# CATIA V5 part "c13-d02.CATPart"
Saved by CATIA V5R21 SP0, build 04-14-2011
Part number: Part1
Bounding box of the stored display mesh (mm): x -33 to 33, y -200.819 to 48, z -35 to 35
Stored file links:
  D:\CATIA V5R21 E-RESOURCES\CATIA-V5R21\catia-v5r21-prt\c13-catia-v5r20-prt\c13-catia-v5r20-figr-13-12 & 13\cat_v5r21_c13-d02.CATPart
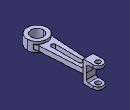
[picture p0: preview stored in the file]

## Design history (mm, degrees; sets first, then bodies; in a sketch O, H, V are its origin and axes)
Body1 (main body)
  Sketch1 on yz-plane, origin (0, 0, 0), H (0, 1, 0), V (0, 0, 1)
    line L1 (0, 0) -> (0, -35)
    point P1 (0, -35)
    line L2 (0, -35) -> (48, -35)
    point P2 (48, -35)
    line L3 (48, -35) -> (48, -25)
    point P3 (48, -25)
    line L4 (48, -25) -> (10, -25)
    point P4 (10, -25)
    line L5 (10, -25) -> (10, 0)
    point P5 (10, 0)
    point P6 (0, 0)
    point P7 (0, 0)
    point P8 (0, 35)
    point P9 (48, 35)
    point P10 (48, 25)
    point P11 (10, 25)
    point P12 (10, 0)
    point P13 (0, 0)
    line L6 (0, 0) -> (0, 35)
    line L7 (0, 35) -> (48, 35)
    line L8 (48, 35) -> (48, 25)
    line L9 (48, 25) -> (10, 25)
    line L10 (10, 25) -> (10, 0)
    length L8 = 10
    distance P3 L9 = 50
    length L2 = 48
    distance L10 L6 = 10
    vertical: L1 V, L3 V, L5 V
    horizontal: L2 H, L4 H
    symmetry: O P7 H, P1 P8 H, P2 P9 H, P3 P10 H, P4 P11 H, P5 P12 H, P6 P13 H, L1 L6 H, L2 L7 H, L3 L8 H, L4 L9 H, L5 L10 H
    coincidence: P13 P7, P12 P5, P6 P7
  Pad1: profile Sketch1, direction (1, 0, 0), length 16, mirrored extent
  Sketch2 on xy-plane, origin (0, 0, 0), H (1, 0, 0), V (0, 1, 0)
    circle A1 centre (0, -168) radius 33
    point P1 (0, -168)
    circle A2 centre (0, -168) radius 20
    distance P1 H = 168
    radius A1 = 33
    radius A2 = 20
    coincidence: P1 V
  Pad2: profile Sketch2, direction (0, 0, 1), length 16, mirrored extent
  Sketch3 on xy-plane, origin (0, 0, 0), H (1, 0, 0), V (0, 1, 0)
    line L1 (-16, 0) -> (-25, -146.4593)
    point P1 (-16, 0)
    point P2 (-25, -146.4593)
    line L2 (16, 0) -> (25, -146.4593)
    point P3 (16, 0)
    point P4 (25, -146.4593)
    reference projected line E1 (16, 48) -> (16, 0) from edge [face of Pad1 | face of Pad1]
    reference projected line E2 (-16, 48) -> (-16, 0) from edge [face of Pad1 | face of Pad1]
    projected circle E3 centre (0, -168) radius 33 from edge [face of Pad2 | face of Pad2]
    projected arc E4 centre (0, -168) radius 33 from (25, -146.4593) to (-25, -146.4593) ccw from edge [face of Pad2 | face of Pad2]
    line L3 (-16, 0) -> (16, 0)
    distance P4 P2 H = 50
    coincidence: P1 H, P3 H, P3 E1, P1 E2, P2 E3, P4 E3
    symmetry: P4 P2 V
    horizontal: L3 H
  Pad3: profile Sketch3, direction (0, 0, 1), length 8, mirrored extent
  Fillet1: radius 6, on edge [face of Pad1 | face of Pad3]; edge [face of Pad3 | face of Pad1]; edge [face of Pad1 | face of Pad1] (x2)
  Fillet2: radius 30, on edge [face of Pad3 | face of Pad2]; edge [face of Pad2 | face of Pad3]
  TritangentFillet1: Face1 face of Pad1, Face2 face of Pad1, RemoveFace face of Pad1
  TritangentFillet2: Face1 face of Pad1, Face2 face of Pad1, RemoveFace face of Pad1
  Sketch4 on face of Pad1, origin (2.8418, 32, 35), H (1, 0, 0), V (0, 1, 0)
    point P1 (-2.8418, 0)
    reference projected arc E1 centre (-2.8418, 0) radius 16 from (13.1582, 0) to (-18.8418, 0) ccw from edge [face of Pad1 | face of TritangentFillet1]
    concentricity: P1 E1
  Hole1: placed by Sketch4, at (0, 32, 35) direction (0, 0, -1), diameter 16, through (limit type 3)
  Sketch5 on face of Pad3, origin (0, 0, 8), H (1, 0, 0), V (0, 1, 0)
    construction line L1 (0, -25) -> (0, -115)
    point P1 (0, -25)
    line L2 (7, -25) -> (7, -115)
    line L3 (-7, -115) -> (-7, -25)
    arc A1 centre (0, -115) radius 7 from (7, -115) to (-7, -115) cw
    arc A2 centre (0, -25) radius 7 from (-7, -25) to (7, -25) cw
    distance P1 H = 25
    length L1 = 90
    radius A1 = 7
    coincidence: P1 V
    vertical: L1 V
    tangency: A1 L2, A2 L2, A1 L3, A2 L3
    parallelism: L1 L2
  Pocket1: profile Sketch5, direction (0, 0, -1), through (limit type 3)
